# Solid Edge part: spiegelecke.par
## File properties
Author: Dieter
Template: Normal.par
Last saved by: Dieter
Revision: 1
Application: Solid Edge
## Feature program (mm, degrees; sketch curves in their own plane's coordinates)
sketch for "unnamed Protrusion 1" plane through (0, 0, 0) normal (0, 0, 1) x-axis (1, 0, 0)
  line (-250, -250) -> (250, -250)
  line (250, -250) -> (250, 250)
  line (250, 250) -> (-250, 250)
  line (-250, 250) -> (-250, -250)
extrude "unnamed Protrusion 1" add finite 2 along +normal
sketch for "unnamed Protrusion 2" plane through (0, 0, 2) normal (0, 0, 1) x-axis (1, 0, 0)
  line (-250, -250) -> (-225.2903, 60.3871)
  line (-225.2903, 60.3871) -> (-83.6129, 197.4194)
  line (-83.6129, 197.4194) -> (250, 250)
  line (250, 250) -> (250, 237.2853)
  line (250, 237.2853) -> (-83.6129, 184.3775)
  line (-83.6129, 184.3775) -> (-216.7574, 51.0984)
  line (-216.7574, 51.0984) -> (-237.6452, -250)
  line (-237.6452, -250) -> (-250, -250)
extrude "unnamed Protrusion 2" add finite 300 along +normal
sketch for "unnamed Cutout 1" plane through (6.1774, -6.3573, 2) normal (0, 0, 1) x-axis (1, 0, 0)
  line (-256.1774, -243.6427) -> (-231.4677, 66.7444)
  line (-231.4677, 66.7444) -> (-89.7903, 203.7767)
  line (-89.7903, 203.7767) -> (243.8226, 256.3573)
  line (243.8226, 256.3573) -> (-256.1774, 256.3573)
  line (-256.1774, 256.3573) -> (-256.1774, -243.6427)
extrude "unnamed Cutout 1" cut finite 603.25 symmetric
